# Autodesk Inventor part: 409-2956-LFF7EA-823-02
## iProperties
Created: 2010-11
Part Number: 409-2956-LFF7EA-823-02
Material: 3/8" OD TUBE - SS
Document SubType Name: Modeling
Designer: S. Boerckel
Engineer: Steve Boerckel
Mass: 375.56 g
Surface Area: 813.903 cm^2
Volume: 46.4802 cm^3
Density: 8.08 g/cm^3
Description: PRESSURE DIFF TUBE
Length: 56.262 in
Author: S. Boerckel
Revision Number: 0
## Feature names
1. Sweep4
